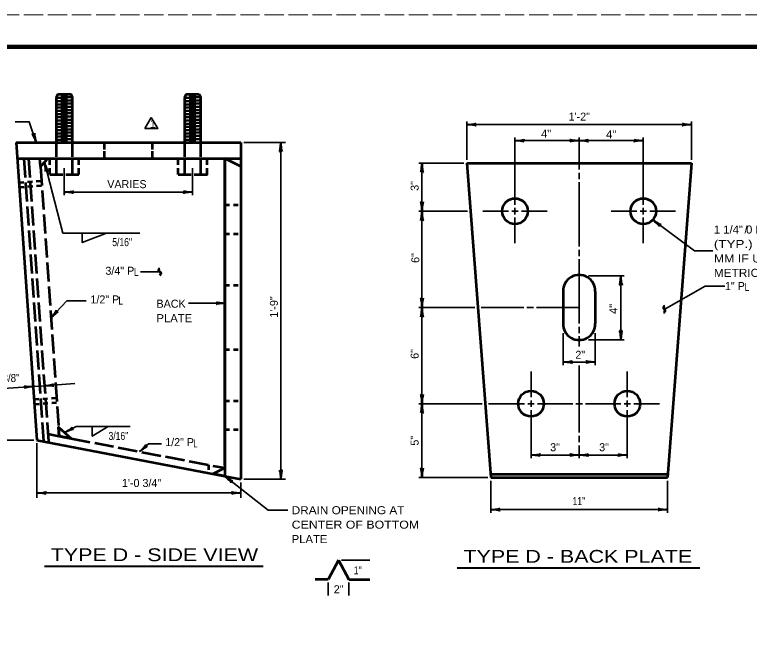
# Model space of a CAD drawing. Extents: x -1 to 679, y 0 to 440.
# Drawn here: x 213.6 to 442.6, y 240.4 to 439.8 of the extents above; entities that cross this region are included whole.
import ezdxf

# ---------------------------------------------------------------- set-up
doc = ezdxf.new("R2010")
doc.units = 0
doc.linetypes.add('LONG_DASHED', pattern=[7.5, 6, -1.5])
doc.linetypes.add('SHORT_DASHED', pattern=[2.7, 1.5, -1.2])
doc.layers.add('1', color=7, linetype='Continuous', lineweight=35)
doc.layers.add('61', color=7, linetype='Continuous', lineweight=35)

msp = doc.modelspace()

# ---------------------------------------------------------------- linework, layer by layer
at = {"layer": '1', "lineweight": 53}
for p, q in [((227.108, 414.992), (226.608, 413.992)), ((228.061, 414.411), (230.069, 414.587)), ((267.108, 414.992), (266.608, 413.992)), ((267.108, 414.992), (271.108, 414.992)), ((268.061, 414.411), (270.069, 414.587)), ((271.108, 414.992), (271.608, 413.992)), ((226.608, 413.992), (226.608, 399.992)), ((227.108, 413.826), (231.108, 414.176)), ((227.108, 412.822), (231.108, 413.172)), ((228.061, 413.408), (230.069, 413.583)), ((228.061, 412.404), (230.069, 412.579)), ((231.608, 413.992), (231.608, 399.992)), ((266.608, 413.992), (266.608, 399.992)), ((267.108, 413.826), (271.108, 414.176)), ((267.108, 412.822), (271.108, 413.172)), ((268.061, 413.408), (270.069, 413.583)), ((268.061, 412.404), (270.069, 412.579)), ((271.608, 413.992), (271.608, 399.992)), ((227.108, 411.819), (231.108, 412.169)), ((227.108, 410.815), (231.108, 411.165)), ((227.108, 409.811), (231.108, 410.161)), ((228.061, 411.4), (230.069, 411.576)), ((228.061, 410.396), (230.069, 410.572)), ((267.108, 411.819), (271.108, 412.169)), ((267.108, 410.815), (271.108, 411.165)), ((267.108, 409.811), (271.108, 410.161)), ((268.061, 411.4), (270.069, 411.576)), ((268.061, 410.396), (270.069, 410.572)), ((227.108, 408.807), (231.108, 409.157)), ((227.108, 407.803), (231.108, 408.153)), ((228.061, 409.392), (230.069, 409.568)), ((228.061, 408.388), (230.069, 408.564)), ((267.108, 408.807), (271.108, 409.157)), ((267.108, 407.803), (271.108, 408.153)), ((268.061, 409.392), (270.069, 409.568)), ((268.061, 408.388), (270.069, 408.564)), ((227.108, 406.799), (231.108, 407.149)), ((227.108, 405.796), (231.108, 406.146)), ((228.061, 407.385), (230.069, 407.56)), ((228.061, 406.381), (230.069, 406.557)), ((228.061, 405.377), (230.069, 405.553)), ((267.108, 406.799), (271.108, 407.149)), ((267.108, 405.796), (271.108, 406.146)), ((268.061, 407.385), (270.069, 407.56)), ((268.061, 406.381), (270.069, 406.557)), ((268.061, 405.377), (270.069, 405.553)), ((227.108, 404.792), (231.108, 405.142)), ((227.108, 403.788), (231.108, 404.138)), ((227.108, 402.784), (231.108, 403.134)), ((228.061, 404.373), (230.069, 404.549)), ((228.061, 403.369), (230.069, 403.545)), ((267.108, 404.792), (271.108, 405.142)), ((267.108, 403.788), (271.108, 404.138)), ((267.108, 402.784), (271.108, 403.134)), ((268.061, 404.373), (270.069, 404.549)), ((268.061, 403.369), (270.069, 403.545)), ((227.108, 401.78), (231.108, 402.13)), ((227.108, 400.777), (231.108, 401.126)), ((228.061, 402.365), (230.069, 402.541)), ((228.061, 401.362), (230.069, 401.537)), ((267.108, 401.78), (271.108, 402.13)), ((267.108, 400.777), (271.108, 401.126)), ((268.061, 402.365), (270.069, 402.541)), ((268.061, 401.362), (270.069, 401.537)), ((214.108, 399.992), (284.108, 399.992)), ((214.108, 399.992), (220.596, 307.218)), ((226.608, 399.492), (226.608, 395.492)), ((228.061, 400.358), (230.069, 400.534)), ((231.608, 399.492), (231.608, 395.492)), ((241.608, 397.742), (241.608, 399.992)), ((256.608, 397.742), (256.608, 399.992)), ((266.608, 399.492), (266.608, 395.492)), ((268.061, 400.358), (270.069, 400.534)), ((271.608, 399.492), (271.608, 395.492)), ((241.608, 394.992), (241.608, 397.242)), ((256.608, 394.992), (256.608, 397.242)), ((214.458, 394.992), (223.975, 394.992)), ((221.649, 392.498), (221.475, 394.992)), ((223.975, 394.992), (284.108, 394.992)), ((224.608, 392.992), (224.608, 394.992)), ((226.608, 394.992), (226.608, 389.992)), ((231.608, 394.992), (231.608, 389.992)), ((233.608, 392.992), (233.608, 394.992)), ((264.608, 392.992), (264.608, 394.992)), ((266.608, 394.992), (266.608, 389.992)), ((271.608, 394.992), (271.608, 389.992)), ((273.608, 392.992), (273.608, 394.992)), ((279.108, 394.992), (279.108, 295.954)), ((279.108, 299.344), (279.108, 394.992)), ((224.608, 389.992), (224.608, 391.992)), ((233.608, 389.992), (233.608, 391.992)), ((264.608, 389.992), (264.608, 391.992)), ((354.605, 393.532), (424.605, 393.532)), ((354.605, 393.532), (362.105, 295.532)), ((424.605, 393.532), (417.105, 295.532)), ((224.608, 389.992), (228.608, 389.992)), ((229.608, 389.992), (233.608, 389.992)), ((264.608, 389.992), (268.608, 389.992)), ((384.605, 353.532), (384.605, 343.532)), ((394.605, 353.532), (394.605, 343.532)), ((227.338, 311.142), (227.528, 308.43)), ((220.596, 307.218), (279.108, 295.954)), ((227.528, 308.429), (231.197, 307.723)), ((279.108, 295.954), (284.108, 294.992)), ((362.028, 296.532), (417.181, 296.532)), ((362.105, 295.532), (417.105, 295.532)), ((314.572, 269.778), (311.322, 263.778)), ((314.572, 269.778), (317.822, 263.778)), ((311.322, 263.778), (307.322, 263.778)), ((317.822, 263.778), (324.322, 263.778))]:
    msp.add_line(p, q, dxfattribs=at)
at = {"layer": '1'}
for p, q in [((256.216, 407.761), (254.216, 404.297)), ((354.605, 394.532), (354.605, 406.532)), ((354.605, 405.532), (424.605, 405.532)), ((424.605, 394.532), (424.605, 406.532)), ((369.605, 380.532), (369.605, 401.532)), ((389.605, 401.532), (389.605, 391.532)), ((409.605, 380.532), (409.605, 401.532)), ((285.108, 399.992), (298.108, 399.992)), ((296.608, 399.992), (296.608, 294.992)), ((229.108, 391.992), (229.108, 383.492)), ((269.108, 391.992), (269.108, 383.492)), ((353.605, 393.532), (339.605, 393.532)), ((389.605, 390.532), (389.605, 388.532)), ((389.605, 387.532), (389.605, 367.532)), ((229.108, 384.492), (269.108, 384.492)), ((354.753, 378.532), (339.605, 378.532)), ((367.605, 378.532), (359.605, 378.532)), ((368.605, 378.532), (370.605, 378.532)), ((369.605, 379.532), (369.605, 377.532)), ((371.605, 378.532), (379.605, 378.532)), ((407.605, 378.532), (399.605, 378.532)), ((408.605, 378.532), (410.605, 378.532)), ((409.605, 379.532), (409.605, 377.532)), ((411.605, 378.532), (419.605, 378.532)), ((369.605, 376.532), (369.605, 368.532)), ((409.605, 376.532), (409.605, 368.532)), ((389.605, 366.532), (389.605, 364.532)), ((258.866, 359.609), (252.861, 359.609)), ((392.469, 358.4), (403.605, 358.4)), ((402.605, 358.4), (402.605, 338.4)), ((279.316, 349.858), (267.811, 349.858)), ((339.605, 348.532), (357.049, 348.532)), ((359.049, 348.532), (372.327, 348.532)), ((373.327, 348.532), (375.327, 348.532)), ((376.327, 348.532), (389.605, 348.532)), ((389.605, 342.532), (389.605, 340.532)), ((384.605, 340.532), (384.605, 330.532)), ((394.605, 340.532), (394.605, 330.532)), ((392.469, 338.4), (403.605, 338.4)), ((384.605, 331.532), (394.605, 331.532)), ((389.605, 330.4), (389.605, 309.532)), ((374.605, 320.532), (374.605, 328.532)), ((404.605, 320.532), (404.605, 328.532)), ((208.456, 323.135), (219.429, 323.902)), ((219.429, 323.902), (222.921, 324.147)), ((222.921, 324.147), (232.397, 324.809)), ((359.345, 318.532), (339.605, 318.532)), ((372.605, 318.532), (361.345, 318.532)), ((373.605, 318.532), (375.605, 318.532)), ((374.605, 317.532), (374.605, 319.532)), ((376.605, 318.532), (387.605, 318.532)), ((388.605, 318.532), (390.605, 318.532)), ((391.605, 318.532), (402.605, 318.532)), ((403.605, 318.532), (405.605, 318.532)), ((404.605, 317.532), (404.605, 319.532)), ((406.605, 318.532), (414.605, 318.532)), ((374.605, 316.532), (374.605, 301.532)), ((404.605, 316.532), (404.605, 301.532)), ((219.596, 307.218), (201.108, 307.218)), ((389.605, 308.532), (389.605, 306.532)), ((220.596, 306.218), (220.596, 289.218)), ((389.605, 305.532), (389.605, 301.532)), ((361.105, 295.532), (339.605, 295.532)), ((284.108, 293.992), (284.108, 289.218)), ((285.108, 294.992), (298.108, 294.992)), ((362.105, 294.532), (362.105, 284.532)), ((417.105, 294.532), (417.105, 284.532)), ((220.596, 290.718), (284.108, 290.718)), ((362.105, 285.532), (417.105, 285.532)), ((315.572, 269.778), (324.322, 269.778)), ((311.322, 262.778), (311.322, 258.778)), ((317.822, 262.778), (317.822, 258.778))]:
    msp.add_line(p, q, dxfattribs=at)
at = {"layer": '1', "linetype": 'LONG_DASHED', "lineweight": 53}
for p, q in [((216.463, 394.992), (222.628, 306.827)), ((217.967, 394.992), (224.152, 306.534)), ((221.649, 392.498), (227.336, 311.173)), ((223.972, 309.114), (227.528, 308.43)), ((231.21, 307.721), (279.108, 298.5))]:
    msp.add_line(p, q, dxfattribs=at)
at = {"layer": '1', "linetype": 'SHORT_DASHED', "lineweight": 53}
for p, q in [((214.981, 387.52), (221.963, 388.009)), ((215.085, 386.024), (222.068, 386.512)), ((279.108, 380.473), (284.108, 380.473)), ((279.108, 371.473), (284.108, 371.473)), ((279.108, 355.473), (284.108, 355.473)), ((279.108, 335.473), (284.108, 335.473)), ((219.708, 319.912), (226.691, 320.4)), ((219.813, 318.416), (226.796, 318.904)), ((279.108, 319.473), (284.108, 319.473)), ((279.108, 310.473), (284.108, 310.473)), ((274.108, 299.463), (274.108, 296.917))]:
    msp.add_line(p, q, dxfattribs=at)
at = {"layer": '1', "lineweight": 40}
for p, q in [((222.903, 267.877), (291.098, 267.877)), ((351.551, 267.371), (427.241, 267.371))]:
    msp.add_line(p, q, dxfattribs=at)
at = {"layer": '1', "lineweight": 53}
for points in [[(227.108, 414.992), (231.108, 414.992), (231.608, 413.992)], [(284.108, 399.992), (284.108, 394.992), (284.108, 294.992)], [(269.608, 389.992), (273.608, 389.992), (273.608, 391.992)]]:
    msp.add_lwpolyline(points, dxfattribs=at)
at = {"layer": '1'}
for points in [[(256.216, 407.761), (258.216, 404.297), (254.216, 404.297)], [(220.374, 399.992), (218.158, 406.422), (213.801, 406.422)], [(369.605, 400.532), (389.605, 400.532), (409.605, 400.532)], [(222.902, 393.841), (228.694, 371.736), (252.694, 371.736)], [(340.605, 393.532), (340.605, 378.532), (340.605, 348.532), (340.605, 318.532), (340.605, 295.532)], [(412.558, 375.835), (425.578, 366.187), (431.257, 366.187)], [(234.694, 371.736), (234.694, 368.736), (242.225, 371.736)], [(389.605, 363.532), (389.605, 358.664), (389.605, 343.532)], [(416.14, 347.947), (428.922, 355.156), (435.045, 355.156)], [(224.947, 345.335), (229.939, 350.577), (235.931, 350.577)], [(389.605, 339.532), (389.605, 338.4), (389.605, 336.4)], [(229.215, 309.499), (232.845, 311.464), (249.686, 311.464)], [(237.845, 311.464), (237.845, 308.464), (242.791, 311.464)], [(252.597, 303.604), (255.346, 305.979), (259.421, 305.979)], [(374.605, 302.532), (389.605, 302.532), (404.605, 302.532)], [(279.108, 295.954), (292.639, 285.394), (298.764, 285.394)]]:
    msp.add_lwpolyline(points, dxfattribs=at)
at = {"layer": '1', "lineweight": 53}
for points in [[(221.475, 394.992), (223.975, 394.992), (221.649, 392.498)], [(279.108, 394.992), (284.108, 394.992), (284.108, 392.492)], [(227.528, 308.43), (227.336, 311.173), (231.21, 307.721)], [(275.426, 296.663), (279.108, 298.5), (279.108, 295.954)]]:
    msp.add_lwpolyline(points, close=True, dxfattribs=at)
for centre in [(369.605, 378.532), (409.605, 378.532), (374.605, 318.532), (404.605, 318.532)]:
    msp.add_circle(centre, 4, dxfattribs=at)
for centre, radius, start, end in [((258.988, 360.107), 0.513, 101.71531, 256.28469), ((258.745, 359.111), 0.513, 281.71531, 76.28469), ((389.605, 353.663), 5.002, 358.50341, 181.49658), ((416.354, 348.413), 0.513, 90.71531, 245.28469), ((415.925, 347.482), 0.513, 270.71531, 65.28469), ((389.605, 343.402), 5.002, 178.50342, 1.49659)]:
    msp.add_arc(centre, radius, start, end, dxfattribs=at)
at = {"layer": '1', "lineweight": 40}
for centre, major_axis, ratio, start_param, end_param in [((355.725, 405.321), (-1.756, 0.176), 0.07063, 3.1407148, 5.41811), ((355.725, 405.321), (-1.756, 0.176), 0.07063, 3.1407148, 5.41811), ((355.696, 405.808), (-1.786, -0.156), 0.122415, 0.8963533, 3.1415927), ((355.696, 405.808), (-1.786, -0.156), 0.122415, 0.8963533, 3.1415927), ((423.514, 405.256), (1.786, 0.156), 0.122415, 0.8963533, 3.1415927), ((423.484, 405.744), (1.756, -0.176), 0.07063, 3.1407148, 5.41811), ((219.758, 400.933), (0.73, -1.637), 0.122415, 0.8963533, 3.1415927), ((220.209, 401.12), (0.406, -1.718), 0.07063, 3.1407148, 5.41811), ((370.696, 400.808), (-1.786, -0.156), 0.122415, 0.8963533, 3.1415927), ((388.484, 400.744), (1.756, -0.176), 0.07063, 3.1407148, 5.41811), ((388.484, 400.744), (1.756, -0.176), 0.07063, 3.1407148, 5.41811), ((390.696, 400.808), (-1.786, -0.156), 0.122415, 0.8963533, 3.1415927), ((390.696, 400.808), (-1.786, -0.156), 0.122415, 0.8963533, 3.1415927), ((408.484, 400.744), (1.756, -0.176), 0.07063, 3.1407148, 5.41811), ((296.397, 398.871), (0.176, 1.756), 0.07063, 3.1407148, 5.41811), ((296.397, 398.871), (0.176, 1.756), 0.07063, 3.1407148, 5.41811), ((296.885, 398.901), (-0.156, 1.786), 0.122415, 0.8963533, 3.1415927), ((296.885, 398.901), (-0.156, 1.786), 0.122415, 0.8963533, 3.1415927), ((370.725, 400.321), (-1.756, 0.176), 0.07063, 3.1407148, 5.41811), ((388.514, 400.256), (1.786, 0.156), 0.122415, 0.8963533, 3.1415927), ((388.514, 400.256), (1.786, 0.156), 0.122415, 0.8963533, 3.1415927), ((390.725, 400.321), (-1.756, 0.176), 0.07063, 3.1407148, 5.41811), ((390.725, 400.321), (-1.756, 0.176), 0.07063, 3.1407148, 5.41811), ((408.514, 400.256), (1.786, 0.156), 0.122415, 0.8963533, 3.1415927), ((222.981, 392.703), (0.275, -1.744), 0.07063, 6.2823074, 8.5597026), ((223.446, 392.855), (-0.604, 1.688), 0.122415, 0.8963533, 3.1415927), ((340.393, 392.412), (0.176, 1.756), 0.07063, 3.1407148, 5.41811), ((340.881, 392.441), (-0.156, 1.786), 0.122415, 0.8963533, 3.1415927), ((230.2, 384.768), (-1.786, -0.156), 0.122415, 0.8963533, 3.1415927), ((230.2, 384.768), (-1.786, -0.156), 0.122415, 0.8963533, 3.1415927), ((267.988, 384.703), (1.756, -0.176), 0.07063, 3.1407148, 5.41811), ((230.229, 384.28), (-1.756, 0.176), 0.07063, 3.1407148, 5.41811), ((230.229, 384.28), (-1.756, 0.176), 0.07063, 3.1407148, 5.41811), ((268.017, 384.215), (1.786, 0.156), 0.122415, 0.8963533, 3.1415927), ((340.329, 379.623), (0.156, -1.786), 0.122415, 0.8963533, 3.1415927), ((340.816, 379.653), (-0.176, -1.756), 0.07063, 3.1407148, 5.41811), ((340.393, 377.412), (0.176, 1.756), 0.07063, 3.1407148, 5.41811), ((340.881, 377.441), (-0.156, 1.786), 0.122415, 0.8963533, 3.1415927), ((413.333, 374.998), (-1.307, 1.187), 0.07063, 3.1407148, 5.41811), ((413.6, 375.407), (-1.528, 0.938), 0.122415, 0.8963533, 3.1415927), ((402.393, 357.279), (0.176, 1.756), 0.07063, 3.1407148, 5.41811), ((402.393, 357.279), (0.176, 1.756), 0.07063, 3.1407148, 5.41811), ((402.881, 357.309), (-0.156, 1.786), 0.122415, 0.8963533, 3.1415927), ((402.881, 357.309), (-0.156, 1.786), 0.122415, 0.8963533, 3.1415927), ((340.329, 349.623), (0.156, -1.786), 0.122415, 0.8963533, 3.1415927), ((340.816, 349.653), (-0.176, -1.756), 0.07063, 3.1407148, 5.41811), ((278.225, 349.582), (1.786, 0.156), 0.122415, 0.8963533, 3.1415927), ((278.196, 350.07), (1.756, -0.176), 0.07063, 3.1407148, 5.41811), ((340.393, 347.412), (0.176, 1.756), 0.07063, 3.1407148, 5.41811), ((340.881, 347.441), (-0.156, 1.786), 0.122415, 0.8963533, 3.1415927), ((225.5, 346.316), (-1.118, -1.401), 0.122415, 0.8963533, 3.1415927), ((225.873, 346.001), (1.338, 1.151), 0.07063, 6.2823074, 8.5597026), ((402.329, 339.491), (0.156, -1.786), 0.122415, 0.8963533, 3.1415927), ((402.816, 339.52), (-0.176, -1.756), 0.07063, 3.1407148, 5.41811), ((385.725, 331.321), (-1.756, 0.176), 0.07063, 3.1407148, 5.41811), ((385.725, 331.321), (-1.756, 0.176), 0.07063, 3.1407148, 5.41811), ((385.696, 331.808), (-1.786, -0.156), 0.122415, 0.8963533, 3.1415927), ((385.696, 331.808), (-1.786, -0.156), 0.122415, 0.8963533, 3.1415927), ((393.514, 331.256), (1.786, 0.156), 0.122415, 0.8963533, 3.1415927), ((393.484, 331.744), (1.756, -0.176), 0.07063, 3.1407148, 5.41811), ((218.297, 324.035), (1.764, -0.053), 0.07063, 3.1407148, 5.41811), ((218.36, 323.551), (1.77, 0.28), 0.122415, 0.8963533, 3.1415927), ((223.99, 324.498), (-1.77, -0.28), 0.122415, 0.8963533, 3.1415927), ((223.99, 324.498), (-1.77, -0.28), 0.122415, 0.8963533, 3.1415927), ((224.053, 324.014), (-1.764, 0.053), 0.07063, 3.1407148, 5.41811), ((224.053, 324.014), (-1.764, 0.053), 0.07063, 3.1407148, 5.41811), ((340.329, 319.623), (0.156, -1.786), 0.122415, 0.8963533, 3.1415927), ((340.816, 319.653), (-0.176, -1.756), 0.07063, 3.1407148, 5.41811), ((340.393, 317.412), (0.176, 1.756), 0.07063, 3.1407148, 5.41811), ((340.881, 317.441), (-0.156, 1.786), 0.122415, 0.8963533, 3.1415927), ((230.043, 310.262), (-1.496, -0.987), 0.122415, 0.8963533, 3.1415927), ((230.301, 309.846), (-1.628, -0.681), 0.07063, 3.1407148, 5.41811), ((253.242, 304.526), (-1.249, -1.286), 0.122415, 0.8963533, 3.1415927), ((253.583, 304.176), (-1.444, -1.015), 0.07063, 3.1407148, 5.41811), ((375.725, 302.321), (-1.756, 0.176), 0.07063, 3.1407148, 5.41811), ((375.725, 302.321), (-1.756, 0.176), 0.07063, 3.1407148, 5.41811), ((375.696, 302.808), (-1.786, -0.156), 0.122415, 0.8963533, 3.1415927), ((375.696, 302.808), (-1.786, -0.156), 0.122415, 0.8963533, 3.1415927), ((388.514, 302.256), (1.786, 0.156), 0.122415, 0.8963533, 3.1415927), ((388.514, 302.256), (1.786, 0.156), 0.122415, 0.8963533, 3.1415927), ((388.484, 302.744), (1.756, -0.176), 0.07063, 3.1407148, 5.41811), ((388.484, 302.744), (1.756, -0.176), 0.07063, 3.1407148, 5.41811), ((390.725, 302.321), (-1.756, 0.176), 0.07063, 3.1407148, 5.41811), ((390.725, 302.321), (-1.756, 0.176), 0.07063, 3.1407148, 5.41811), ((390.696, 302.808), (-1.786, -0.156), 0.122415, 0.8963533, 3.1415927), ((390.696, 302.808), (-1.786, -0.156), 0.122415, 0.8963533, 3.1415927), ((403.514, 302.256), (1.786, 0.156), 0.122415, 0.8963533, 3.1415927), ((403.514, 302.256), (1.786, 0.156), 0.122415, 0.8963533, 3.1415927), ((403.484, 302.744), (1.756, -0.176), 0.07063, 3.1407148, 5.41811), ((403.484, 302.744), (1.756, -0.176), 0.07063, 3.1407148, 5.41811), ((296.332, 296.083), (0.156, -1.786), 0.122415, 0.8963533, 3.1415927), ((296.82, 296.112), (-0.176, -1.756), 0.07063, 3.1407148, 5.41811), ((340.329, 296.623), (0.156, -1.786), 0.122415, 0.8963533, 3.1415927), ((340.816, 296.653), (-0.176, -1.756), 0.07063, 3.1407148, 5.41811), ((279.862, 295.098), (1.277, -1.219), 0.07063, 6.2823074, 8.5597026), ((280.139, 295.501), (-1.504, 0.976), 0.122415, 0.8963533, 3.1415927), ((221.687, 290.995), (-1.786, -0.156), 0.122415, 0.8963533, 3.1415927), ((221.687, 290.995), (-1.786, -0.156), 0.122415, 0.8963533, 3.1415927), ((282.988, 290.93), (1.756, -0.176), 0.07063, 3.1407148, 5.41811), ((282.988, 290.93), (1.756, -0.176), 0.07063, 3.1407148, 5.41811), ((221.716, 290.507), (-1.756, 0.176), 0.07063, 3.1407148, 5.41811), ((221.716, 290.507), (-1.756, 0.176), 0.07063, 3.1407148, 5.41811), ((283.017, 290.442), (1.786, 0.156), 0.122415, 0.8963533, 3.1415927), ((283.017, 290.442), (1.786, 0.156), 0.122415, 0.8963533, 3.1415927), ((363.225, 285.321), (-1.756, 0.176), 0.07063, 3.1407148, 5.41811), ((363.225, 285.321), (-1.756, 0.176), 0.07063, 3.1407148, 5.41811), ((363.196, 285.808), (-1.786, -0.156), 0.122415, 0.8963533, 3.1415927), ((363.196, 285.808), (-1.786, -0.156), 0.122415, 0.8963533, 3.1415927), ((416.014, 285.256), (1.786, 0.156), 0.122415, 0.8963533, 3.1415927), ((415.984, 285.744), (1.756, -0.176), 0.07063, 3.1407148, 5.41811)]:
    msp.add_ellipse(centre, major_axis=major_axis, ratio=ratio, start_param=start_param, end_param=end_param, dxfattribs=at)
at = {"layer": '61', "linetype": 'LONG_DASHED', "lineweight": 13}
msp.add_line((-0.995, 439.78), (679.025, 439.78), dxfattribs=at)
at = {"layer": '61', "lineweight": 158}
msp.add_lwpolyline([(668.045, 429.78), (29.005, 429.78), (29.005, 9.76)], dxfattribs=at)

# ---------------------------------------------------------------- texts
at = {"layer": '1'}
for s, p in [('1\'-2"', (386.318, 406.758)), ('1', (255.764, 404.499)), ('VARIES', (242.501, 385.716)), ('/', (441.147, 371.541)), ('3/4" P', (241.918, 358.717)), ('1" P', (435.044, 353.956)), ('1/2" P', (237.258, 349.782)), ('BACK', (257.841, 348.447)), ('2"', (388.425, 332.521)), ('1/2" P', (260.56, 305.301)), ('3"', (380.573, 303.722)), ('3"', (395.841, 303.722)), ('1\'-0 3/4"', (247.081, 292.571)), ('2"', (313.108, 259.446))]:
    msp.add_text(s, height=2.5, dxfattribs=at).set_placement(p)
for s, height, width, p in [('4"', 2.5, 1.05, (377.72, 401.403)), ('4"', 2.5, 1.05, (397.999, 401.241)), ('1 1/4" 0 HOLE', 2.5, 1.05, (431.606, 371.566)), ('5/16"', 2.5, 0.8, (244.054, 367.652)), ('(TYP.) OR 30', 2.5, 1.25, (431.606, 367.066)), ('MM IF USE', 2.5, 1.15, (431.606, 362.566)), ('L', 2.5, 0.75, (250.851, 358.328)), ('METRIC BOLT', 2.5, 1.1, (431.606, 358.066)), ('L', 2.5, 0.75, (441.206, 353.684)), ('L', 2.5, 0.75, (245.996, 349.393)), ('PLATE', 2.5, 1.05, (257.841, 343.947)), ('3/8"', 2.5, 0.9, (209.879, 325.308)), ('3/16"', 2.5, 0.8, (242.889, 307.243)), ('L', 2.5, 0.75, (269.298, 304.912)), ('11"', 2.5, 0.8, (387.553, 286.923)), ('DRAIN OPENING AT', 2.5, 1.1, (299.993, 284.088)), ('CENTER OF BOTTOM', 2.5, 1.15, (299.993, 279.588)), ('PLATE', 2.5, 1.05, (299.993, 275.088)), ('TYPE D - SIDE VIEW', 4, 1.25, (224.878, 269.457)), ('TYPE D - BACK PLATE', 4, 1.25, (353.526, 268.952)), ('1"', 2.5, 0.8, (319.359, 265.342))]:
    msp.add_text(s, height=height, dxfattribs=dict(at, width=width)).set_placement(p)
for s, p in [('3"', (339.57, 384.882)), ('6"', (339.788, 362.411)), ('1\'-9"', (295.699, 345.347)), ('6"', (339.57, 332.521)), ('5"', (339.57, 305.467))]:
    msp.add_text(s, height=2.5, rotation=90, dxfattribs=at).set_placement(p)
at = {"layer": '1', "width": 1.05}
msp.add_text('4"', height=2.5, rotation=90, dxfattribs=at).set_placement((401.511, 346.484))

doc.saveas('drawing.dxf')
